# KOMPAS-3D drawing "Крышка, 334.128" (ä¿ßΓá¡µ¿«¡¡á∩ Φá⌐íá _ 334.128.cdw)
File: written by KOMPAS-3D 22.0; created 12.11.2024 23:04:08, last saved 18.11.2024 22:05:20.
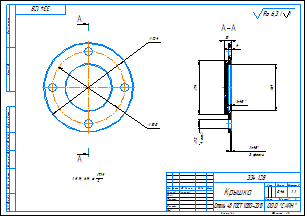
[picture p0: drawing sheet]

Sheet 1: A3, landscape

Document properties: Автор: aleksander.larionov.10@gmail.com; Знак неуказанной шероховатости: 4; Параметр неуказанной шероховатости: Ra 6,3; Полное имя файла: Дистанционная шайба _ 334.128.m3d; Масса: 0.45945

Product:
- Part/product: Крышка  | designation 334.128
    Материал: Сталь 45 ГОСТ 1050-2013 (density 7810 kg/m3)
    Масса: 0.45945

Title block, sheet 1: Наименование: Крышка; designation: 334.128; Материал: Сталь 45 ГОСТ 1050-2013; Масса: 0,46; Количество листов документа: 1; organisation: ООО "САЙН"; Форматы листов документа: A3; stored path: C:\Мои папки\Работа\Чертеж.cdt; Разработал: Ларионов

Views: Вид 1, Сверху, Разрез А-А
Referenced files in C:\Мои папки\Работа\Крышки, фланцы\334.128\: Дистанционная шайба _ 334.128.m3d
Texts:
  Ra 6,3
  Ra 6,3 ( )
Dimensions and other numbers on the sheet: 124; 100; 334.128; 64; 74; 12; 4 отв.; 1; 3 фаски; 4; 10; 1 H14, h14,    IT14 2 .; 1:1; 0,46; 334.128 Крышка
